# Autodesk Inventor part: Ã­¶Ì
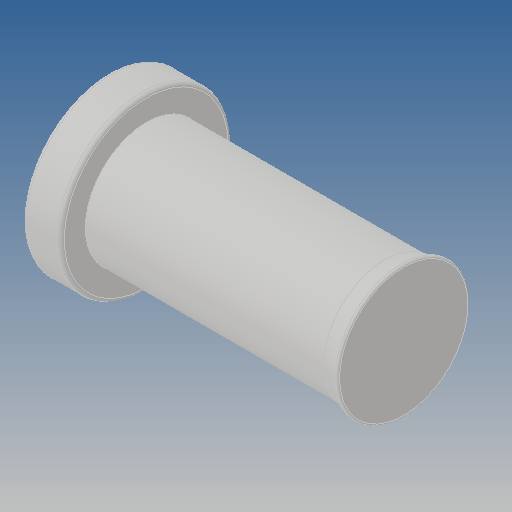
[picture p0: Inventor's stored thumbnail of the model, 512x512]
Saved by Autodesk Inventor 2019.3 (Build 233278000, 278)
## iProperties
Created: 2017-12
Part Number: Ã­¶Ì
Material: Ogólny
Document SubType Name: Modeling
Designer: Admin
Density: 1 g/cm^3
Appearance: Domyślna
Author: Admin
Revision Number: ÈÎºÎ
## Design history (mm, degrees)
feature "Ðý×ª1"
node "Bryła1"
